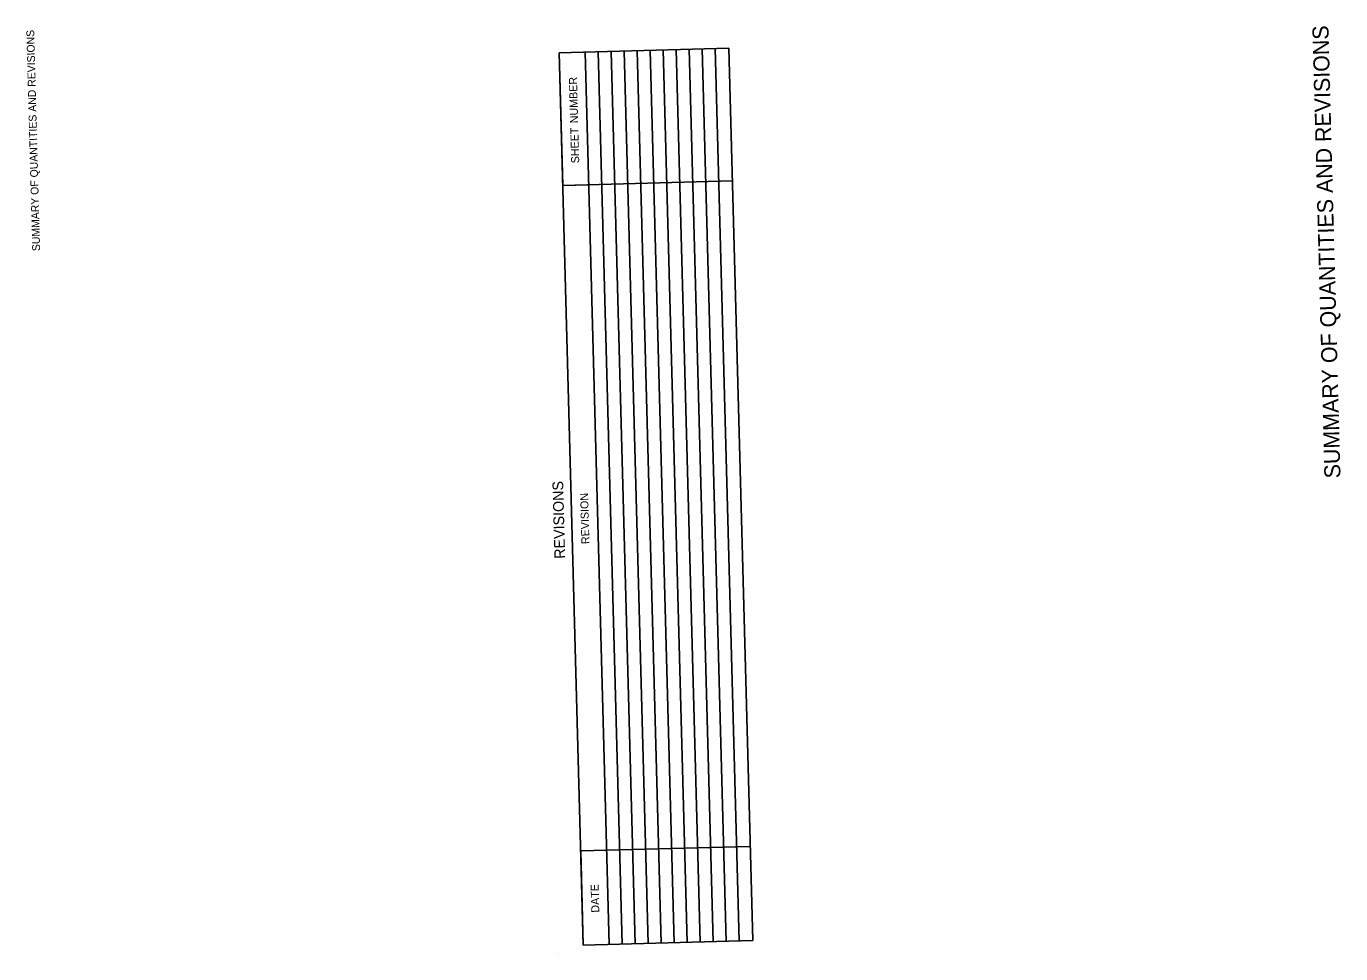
# Model space of a CAD drawing. Extents: x 1930093 to 1931323, y 596452 to 607874.
# Drawn here: x 1930093 to 1931079, y 607178 to 607874 of the extents above; entities that cross this region are included whole.
import ezdxf

# ---------------------------------------------------------------- set-up
doc = ezdxf.new("R2010")
doc.units = 0
for name, color, linetype in [('Default', 7, 'Continuous'), ('R_Border', 7, 'Continuous'), ('R_Border Prem', 7, 'Continuous')]:
    doc.layers.add(name, color=color, linetype=linetype)

msp = doc.modelspace()

# ---------------------------------------------------------------- linework, layer by layer
at = {"layer": 'Default'}
for p, q in [((1930619.96, 607857.3), (1930492.77, 607853.88)), ((1930619.96, 607857.3), (1930492.77, 607853.88)), ((1930549.72, 607185.83), (1930531.76, 607854.93)), ((1930559.47, 607186.09), (1930541.5, 607855.19)), ((1930569.21, 607186.35), (1930551.25, 607855.45)), ((1930578.96, 607186.62), (1930561, 607855.71)), ((1930588.71, 607186.88), (1930570.74, 607855.97)), ((1930598.45, 607187.14), (1930580.49, 607856.24)), ((1930608.2, 607187.4), (1930590.24, 607856.5)), ((1930617.94, 607187.66), (1930599.98, 607856.76)), ((1930627.69, 607187.92), (1930609.73, 607857.02)), ((1930637.93, 607188.2), (1930619.96, 607857.3)), ((1930510.73, 607184.78), (1930492.77, 607853.88)), ((1930495.44, 607754.47), (1930492.77, 607853.88)), ((1930530.23, 607185.31), (1930512.27, 607854.4)), ((1930539.97, 607185.57), (1930522.01, 607854.67)), ((1930622.63, 607757.88), (1930495.44, 607754.47)), ((1930514.93, 607754.99), (1930495.44, 607754.47)), ((1930636.03, 607258.86), (1930508.84, 607255.45)), ((1930510.73, 607184.78), (1930508.84, 607255.45)), ((1930637.93, 607188.2), (1930510.73, 607184.78)), ((1930637.93, 607188.2), (1930510.73, 607184.78))]:
    msp.add_line(p, q, dxfattribs=at)
at = {"layer": 'R_Border'}
msp.add_line((1930491.4, 607178.41), (1930491.4, 607178.41), dxfattribs=at)

# ---------------------------------------------------------------- texts
at = {"layer": 'Default'}
for s, height, p in [(' NUMBER', 6, (1930507, 607798.87)), ('SHEET', 6, (1930507.75, 607771.1)), ('REVISIONS', 8, (1930497.2, 607474.65)), ('REVISION', 6, (1930515.41, 607485.61)), ('DATE', 6, (1930522.83, 607209.26))]:
    msp.add_text(s, height=height, rotation=91.53769, dxfattribs=at).set_placement(p)
at = {"layer": 'R_Border'}
msp.add_text(' SUMMARY OF QUANTITIES AND REVISIONS', height=12, rotation=91.53769, dxfattribs=at).set_placement((1931078.62, 607530.49))
at = {"layer": 'R_Border Prem'}
msp.add_text('SUMMARY OF QUANTITIES AND REVISIONS', height=5.862, rotation=91.53769, dxfattribs=at).set_placement((1930103.54, 607705.23))

doc.saveas('drawing.dxf')
